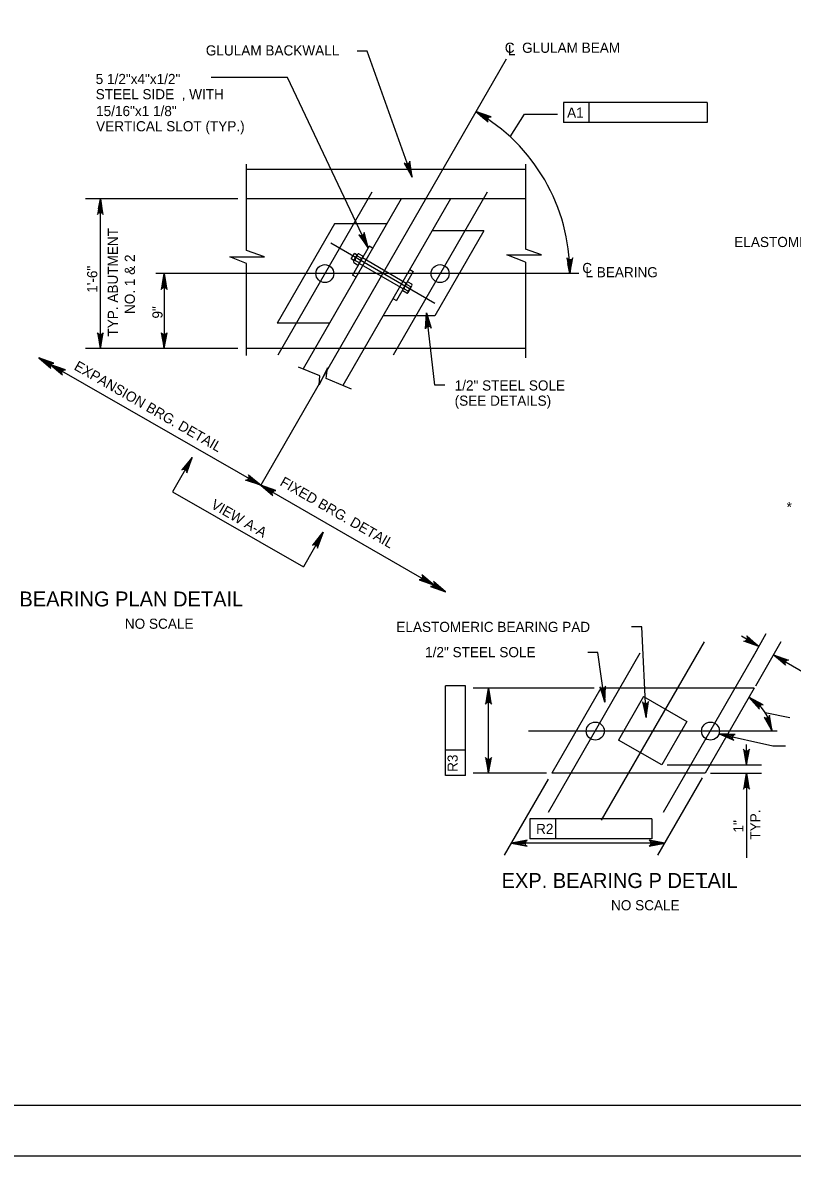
# Model space of a CAD drawing. Extents: x 638263 to 640391, y 293683 to 298655.
# Drawn here: x 638494.1 to 638721.7, y 293683.5 to 294018.7 of the extents above; entities that cross this region are included whole.
import ezdxf

# ---------------------------------------------------------------- set-up
doc = ezdxf.new("R2010")
doc.units = 0
for name, color, linetype in [('2', 7, 'Continuous'), ('3', 7, 'Continuous'), ('4', 7, 'Continuous'), ('5', 7, 'Continuous'), ('PLT-BNDY', 7, 'Continuous')]:
    doc.layers.add(name, color=color, linetype=linetype)

msp = doc.modelspace()

# ---------------------------------------------------------------- linework, layer by layer
at = {"layer": '2'}
msp.add_line((639261.46, 293698.46), (638475.46, 293698.46), dxfattribs=at)
at = {"layer": '3'}
for p, q in [((638637.06, 294007.91), (638564.52, 293881.93)), ((638560.31, 293951.36), (638560.31, 293976.89)), ((638642.78, 293976.89), (638642.78, 293951.74)), ((638642.78, 293975.28), (638560.31, 293975.28)), ((638642.78, 293966.67), (638560.31, 293966.67)), ((638597.37, 293968.64), (638569.6, 293920.41)), ((638606.09, 293966.67), (638577.03, 293916.33)), ((638620.65, 293966.67), (638588.78, 293911.46)), ((638631.45, 293968.64), (638603.67, 293920.41)), ((638586.31, 293959.29), (638569.39, 293929.9)), ((638601.83, 293959.29), (638586.31, 293959.29)), ((638630.52, 293957.16), (638615.17, 293957.16)), ((638630.52, 293957.16), (638616.05, 293932.03)), ((638616.03, 293935.64), (638585.24, 293953.53)), ((638596.61, 293952.61), (638591.69, 293944.08)), ((638597.61, 293952.03), (638596.61, 293952.61)), ((638560.31, 293947.52), (638555.4, 293949.52)), ((638555.4, 293949.52), (638565.67, 293949.52)), ((638565.67, 293949.52), (638560.31, 293951.36)), ((638591.3, 293948.86), (638592.23, 293950.46)), ((638592.09, 293948.41), (638591.3, 293948.86)), ((638591.99, 293948.23), (638593.12, 293950.2)), ((638593.01, 293950.01), (638592.23, 293950.46)), ((638594.27, 293949.08), (638593.15, 293949.72)), ((638593.54, 293950.39), (638594.66, 293949.75)), ((638593.56, 293947.32), (638594.7, 293949.29)), ((638607.56, 293941.63), (638594.61, 293949.15)), ((638637.27, 293950.11), (638647.54, 293950.11)), ((638642.78, 293947.87), (638637.27, 293950.11)), ((638647.54, 293950.11), (638642.78, 293951.74)), ((638560.31, 293920.34), (638560.31, 293947.52)), ((638592.04, 293947.8), (638593.16, 293947.16)), ((638593.52, 293947.78), (638592.4, 293948.42)), ((638606.63, 293940.01), (638593.68, 293947.53)), ((638608.58, 293945.7), (638609.58, 293945.12)), ((638642.78, 293947.87), (638642.78, 293919.65)), ((638592.73, 293943.48), (638591.69, 293944.08)), ((638609.58, 293945.12), (638604.66, 293936.6)), ((638606.53, 293939.84), (638607.66, 293941.81)), ((638607.7, 293938.76), (638606.58, 293939.41)), ((638606.95, 293940.03), (638608.06, 293939.39)), ((638607.69, 293941.33), (638608.81, 293940.69)), ((638609.2, 293941.36), (638608.08, 293942)), ((638608.1, 293938.93), (638609.24, 293940.9)), ((638603.61, 293937.2), (638604.66, 293936.6)), ((638584.86, 293929.9), (638569.39, 293929.9)), ((638616.05, 293932.03), (638600.66, 293932.03)), ((638580.52, 293922.37), (638560.31, 293922.37)), ((638595.08, 293922.37), (638580.52, 293922.37)), ((638642.78, 293922.37), (638595.08, 293922.37)), ((638695.64, 293835.63), (638665.23, 293782.83)), ((638676.62, 293832.26), (638649.47, 293785.12)), ((638711.32, 293833.35), (638683.55, 293785.12)), ((638665.04, 293821.88), (638650.56, 293796.75)), ((638710.39, 293821.88), (638665.04, 293821.88)), ((638710.39, 293821.88), (638695.92, 293796.75)), ((638677.74, 293819.42), (638670.35, 293806.57)), ((638677.74, 293819.42), (638690.54, 293812.05)), ((638690.54, 293812.05), (638683.14, 293799.21)), ((638683.14, 293799.21), (638670.35, 293806.57)), ((638695.92, 293796.75), (638650.56, 293796.75))]:
    msp.add_line(p, q, dxfattribs=at)
for points in [[(638631.86, 293821.88), (638630.99, 293817.22), (638631.24, 293817.57), (638631.55, 293817.76), (638631.86, 293817.81), (638632.17, 293817.76), (638632.49, 293817.57), (638632.73, 293817.22), (638631.86, 293821.88), (638632.49, 293817.57), (638632.17, 293817.76), (638631.86, 293821.88), (638631.86, 293817.81), (638631.55, 293817.76), (638631.86, 293821.88), (638631.24, 293817.57)], [(638666.3, 293817.79), (638666.51, 293822.53), (638666.31, 293822.14), (638666.03, 293821.91), (638665.73, 293821.82), (638665.41, 293821.83), (638665.08, 293821.96), (638664.78, 293822.28), (638666.3, 293817.79), (638665.08, 293821.96), (638665.41, 293821.83), (638666.3, 293817.79), (638665.73, 293821.82), (638666.03, 293821.91), (638666.3, 293817.79), (638666.31, 293822.14)], [(638708.87, 293819.24), (638711.98, 293815.66), (638711.85, 293816.07), (638711.9, 293816.43), (638712.06, 293816.71), (638712.29, 293816.92), (638712.63, 293817.05), (638713.07, 293817.03), (638708.87, 293819.24), (638712.63, 293817.05), (638712.29, 293816.92), (638708.87, 293819.24), (638712.06, 293816.71), (638711.9, 293816.43), (638708.87, 293819.24), (638711.85, 293816.07)], [(638678.54, 293813.27), (638679.18, 293817.97), (638678.95, 293817.59), (638678.64, 293817.39), (638678.34, 293817.33), (638678.02, 293817.36), (638677.7, 293817.53), (638677.43, 293817.88), (638678.54, 293813.27), (638677.7, 293817.53), (638678.02, 293817.36), (638678.54, 293813.27), (638678.34, 293817.33), (638678.64, 293817.39), (638678.54, 293813.27), (638678.95, 293817.59)], [(638715.73, 293809.24), (638715, 293813.92), (638714.89, 293813.5), (638714.65, 293813.22), (638714.38, 293813.07), (638714.07, 293813.01), (638713.71, 293813.08), (638713.36, 293813.34), (638715.73, 293809.24), (638713.71, 293813.08), (638714.07, 293813.01), (638715.73, 293809.24), (638714.38, 293813.07), (638714.65, 293813.22), (638715.73, 293809.24), (638714.89, 293813.5)], [(638700.03, 293808.4), (638704.39, 293806.55), (638704.1, 293806.87), (638703.98, 293807.21), (638704, 293807.53), (638704.12, 293807.82), (638704.36, 293808.09), (638704.77, 293808.25), (638700.03, 293808.4), (638704.36, 293808.09), (638704.12, 293807.82), (638700.03, 293808.4), (638704, 293807.53), (638703.98, 293807.21), (638700.03, 293808.4), (638704.1, 293806.87)], [(638631.86, 293796.75), (638632.73, 293801.41), (638632.49, 293801.05), (638632.17, 293800.86), (638631.86, 293800.81), (638631.55, 293800.86), (638631.24, 293801.05), (638630.99, 293801.41), (638631.86, 293796.75), (638631.24, 293801.05), (638631.55, 293800.86), (638631.86, 293796.75), (638631.86, 293800.81), (638632.17, 293800.86), (638631.86, 293796.75), (638632.49, 293801.05)], [(638708.14, 293799.21), (638709.01, 293803.87), (638708.76, 293803.51), (638708.45, 293803.32), (638708.14, 293803.27), (638707.83, 293803.32), (638707.51, 293803.51), (638707.26, 293803.87), (638708.14, 293799.21), (638707.51, 293803.51), (638707.83, 293803.32), (638708.14, 293799.21), (638708.14, 293803.27), (638708.45, 293803.32), (638708.14, 293799.21), (638708.76, 293803.51)], [(638708.14, 293796.75), (638707.26, 293792.09), (638707.51, 293792.44), (638707.83, 293792.63), (638708.14, 293792.68), (638708.45, 293792.63), (638708.76, 293792.44), (638709.01, 293792.09), (638708.14, 293796.75), (638708.76, 293792.44), (638708.45, 293792.63), (638708.14, 293796.75), (638708.14, 293792.68), (638707.83, 293792.63), (638708.14, 293796.75), (638707.51, 293792.44)], [(638638.65, 293776.05), (638643.31, 293775.18), (638642.95, 293775.43), (638642.76, 293775.74), (638642.71, 293776.05), (638642.76, 293776.36), (638642.95, 293776.68), (638643.31, 293776.92), (638638.65, 293776.05), (638642.95, 293776.68), (638642.76, 293776.36), (638638.65, 293776.05), (638642.71, 293776.05), (638642.76, 293775.74), (638638.65, 293776.05), (638642.95, 293775.43)], [(638684, 293776.05), (638679.34, 293776.92), (638679.7, 293776.68), (638679.89, 293776.36), (638679.94, 293776.05), (638679.89, 293775.74), (638679.7, 293775.43), (638679.34, 293775.18), (638684, 293776.05), (638679.7, 293775.43), (638679.89, 293775.74), (638684, 293776.05), (638679.94, 293776.05), (638679.89, 293776.36), (638684, 293776.05), (638679.7, 293776.68)]]:
    msp.add_lwpolyline(points, dxfattribs=at)
for centre in [(638583.49, 293944.52), (638617.56, 293944.52), (638663.43, 293809.23), (638697.51, 293809.23)]:
    msp.add_circle(centre, 2.66, dxfattribs=at)
for centre, radius, start, end in [((638593.58, 293948.61), 1.19, 111.021, 188.921), ((638593.48, 293949.98), 0.417, 151.798, 218.684), ((638593.48, 293949.98), 0.417, 81.2579, 151.798), ((638593.09, 293948.89), 1.19, 291.021, 8.921), ((638594.33, 293949.49), 0.417, 261.2579, 328.1439), ((638594.33, 293949.49), 0.417, 328.1439, 38.684), ((638592.32, 293948.06), 0.379, 77.4228, 222.5192), ((638593.24, 293947.53), 0.379, 257.4228, 42.5192), ((638606.86, 293939.66), 0.379, 77.4808, 222.5772), ((638608.12, 293940.22), 1.19, 111.079, 188.979), ((638608.02, 293941.59), 0.417, 151.8561, 218.7421), ((638608.02, 293941.59), 0.417, 81.3159, 151.8561), ((638607.78, 293939.13), 0.379, 257.4808, 42.5772), ((638607.63, 293940.5), 1.19, 291.079, 8.979), ((638608.87, 293941.1), 0.417, 261.3159, 328.2019), ((638608.87, 293941.1), 0.417, 328.2019, 38.7421)]:
    msp.add_arc(centre, radius, start, end, dxfattribs=at)
at = {"layer": '4'}
for p, q in [((638596.03, 294010.31), (638593.08, 294010.31)), ((638609.33, 293973.08), (638596.03, 294010.31)), ((638572.41, 294002.56), (638549.84, 294002.56)), ((638596.33, 293952.12), (638572.41, 294002.56)), ((638654.01, 293995.11), (638654.01, 293989.2)), ((638688.96, 293995.11), (638654.01, 293995.11)), ((638661.57, 293995.11), (638654.01, 293995.11)), ((638661.57, 293995.11), (638661.57, 293989.2)), ((638696.53, 293995.11), (638688.96, 293995.11)), ((638696.53, 293995.11), (638696.53, 293989.2)), ((638638.27, 293985.01), (638642.5, 293991.68)), ((638642.5, 293991.68), (638652.23, 293991.68)), ((638696.53, 293989.2), (638654.01, 293989.2)), ((638557.78, 293966.67), (638512.68, 293966.67)), ((638517.11, 293922.37), (638517.11, 293966.67)), ((638658.61, 293944.52), (638533.49, 293944.52)), ((638535.98, 293944.52), (638535.98, 293922.37)), ((638615.97, 293911.53), (638613.59, 293932.97)), ((638557.78, 293922.37), (638512.68, 293922.37)), ((638555.34, 293922.37), (638529.08, 293922.37)), ((638536.42, 293922.37), (638531.55, 293922.37)), ((638555.34, 293922.37), (638531.76, 293922.37)), ((638498.91, 293919.59), (638564.52, 293881.93)), ((638582.02, 293914.29), (638575.7, 293916.88)), ((638584.25, 293916.62), (638581.85, 293911.64)), ((638583.91, 293913.5), (638584.25, 293916.62)), ((638581.85, 293911.64), (638582.02, 293914.29)), ((638591.41, 293910.36), (638583.91, 293913.5)), ((638618.93, 293911.53), (638615.97, 293911.53)), ((638544.27, 293890.12), (638538.45, 293880)), ((638538.45, 293880), (638577.13, 293857.79)), ((638565.18, 293881.55), (638619.21, 293850.37)), ((638582.91, 293867.83), (638577.13, 293857.79)), ((638677.2, 293840.05), (638674.2, 293840.05)), ((638678.54, 293813.27), (638677.2, 293840.05)), ((638711.83, 293834.28), (638706.65, 293837.26)), ((638710.1, 293831.22), (638713.98, 293838.05)), ((638710.91, 293822.59), (638718.36, 293835.71)), ((638664.2, 293832.47), (638661.2, 293832.47)), ((638666.3, 293817.79), (638664.2, 293832.47)), ((638716.15, 293831.82), (638733.44, 293821.66)), ((638619.12, 293796.05), (638619.12, 293822.59)), ((638625.03, 293822.59), (638619.12, 293822.59)), ((638625.03, 293803.61), (638625.03, 293822.59)), ((638663.09, 293821.88), (638627.36, 293821.88)), ((638631.86, 293796.75), (638631.86, 293821.88)), ((638713.63, 293814.72), (638720.94, 293813.26)), ((638717.18, 293809.23), (638643.69, 293809.23)), ((638700.03, 293808.4), (638715.98, 293804.89)), ((638708.14, 293799.21), (638708.14, 293805.21)), ((638715.98, 293804.89), (638719.68, 293804.89)), ((638625.03, 293803.61), (638619.12, 293803.61)), ((638625.03, 293796.05), (638625.03, 293803.61)), ((638684.7, 293799.21), (638712.64, 293799.21)), ((638625.03, 293796.05), (638619.12, 293796.05)), ((638649, 293796.75), (638627.36, 293796.75)), ((638636.63, 293772.54), (638649.58, 293795.04)), ((638681.98, 293772.54), (638695.13, 293795.37)), ((638697.48, 293796.75), (638712.64, 293796.75)), ((638708.14, 293796.75), (638708.14, 293771.78)), ((638644.12, 293783.25), (638644.12, 293777.34)), ((638672.61, 293783.25), (638644.12, 293783.25)), ((638651.68, 293783.25), (638644.12, 293783.25)), ((638651.68, 293783.25), (638651.68, 293777.34)), ((638680.18, 293783.25), (638672.61, 293783.25)), ((638680.18, 293783.25), (638680.18, 293777.34)), ((638684, 293776.05), (638638.65, 293776.05)), ((638680.18, 293777.34), (638644.12, 293777.34))]:
    msp.add_line(p, q, dxfattribs=at)
for points in [[(638628.15, 293992.44), (638631.76, 293989.37), (638631.58, 293989.76), (638631.57, 293990.12), (638631.68, 293990.42), (638631.88, 293990.67), (638632.2, 293990.85), (638632.63, 293990.88), (638628.15, 293992.44), (638632.2, 293990.85), (638631.88, 293990.67), (638628.15, 293992.44), (638631.68, 293990.42), (638631.57, 293990.12), (638628.15, 293992.44), (638631.58, 293989.76)], [(638609.33, 293973.08), (638608.58, 293977.77), (638608.47, 293977.34), (638608.24, 293977.06), (638607.96, 293976.91), (638607.65, 293976.85), (638607.29, 293976.92), (638606.94, 293977.18), (638609.33, 293973.08), (638607.29, 293976.92), (638607.65, 293976.85), (638609.33, 293973.08), (638607.96, 293976.91), (638608.24, 293977.06), (638609.33, 293973.08), (638608.47, 293977.34)], [(638517.11, 293966.67), (638516.23, 293962.01), (638516.48, 293962.37), (638516.79, 293962.55), (638517.11, 293962.61), (638517.42, 293962.55), (638517.73, 293962.37), (638517.98, 293962.01), (638517.11, 293966.67), (638517.73, 293962.37), (638517.42, 293962.55), (638517.11, 293966.67), (638517.11, 293962.61), (638516.79, 293962.55), (638517.11, 293966.67), (638516.48, 293962.37)], [(638596.33, 293952.12), (638595.12, 293956.7), (638595.05, 293956.27), (638594.85, 293955.97), (638594.59, 293955.79), (638594.28, 293955.7), (638593.92, 293955.74), (638593.54, 293955.96), (638596.33, 293952.12), (638593.92, 293955.74), (638594.28, 293955.7), (638596.33, 293952.12), (638594.59, 293955.79), (638594.85, 293955.97), (638596.33, 293952.12), (638595.05, 293956.27)], [(638655.95, 293944.52), (638656.82, 293949.18), (638656.57, 293948.82), (638656.26, 293948.63), (638655.95, 293948.58), (638655.64, 293948.63), (638655.32, 293948.82), (638655.08, 293949.18), (638655.95, 293944.52), (638655.32, 293948.82), (638655.64, 293948.63), (638655.95, 293944.52), (638655.95, 293948.58), (638656.26, 293948.63), (638655.95, 293944.52), (638656.57, 293948.82)], [(638535.98, 293944.52), (638535.11, 293939.86), (638535.36, 293940.22), (638535.67, 293940.4), (638535.98, 293940.46), (638536.29, 293940.4), (638536.61, 293940.22), (638536.85, 293939.86), (638535.98, 293944.52), (638536.61, 293940.22), (638536.29, 293940.4), (638535.98, 293944.52), (638535.98, 293940.46), (638535.67, 293940.4), (638535.98, 293944.52), (638535.36, 293940.22)], [(638613.59, 293932.97), (638614.97, 293928.43), (638614.68, 293928.76), (638614.35, 293928.91), (638614.04, 293928.93), (638613.73, 293928.84), (638613.44, 293928.62), (638613.23, 293928.24), (638613.59, 293932.97), (638613.44, 293928.62), (638613.73, 293928.84), (638613.59, 293932.97), (638614.04, 293928.93), (638614.35, 293928.91), (638613.59, 293932.97), (638614.68, 293928.76)], [(638517.11, 293922.37), (638517.98, 293927.03), (638517.73, 293926.68), (638517.42, 293926.49), (638517.11, 293926.44), (638516.79, 293926.49), (638516.48, 293926.68), (638516.23, 293927.03), (638517.11, 293922.37), (638516.48, 293926.68), (638516.79, 293926.49), (638517.11, 293922.37), (638517.11, 293926.44), (638517.42, 293926.49), (638517.11, 293922.37), (638517.73, 293926.68)], [(638535.98, 293922.37), (638536.85, 293927.03), (638536.61, 293926.68), (638536.29, 293926.49), (638535.98, 293926.44), (638535.67, 293926.49), (638535.36, 293926.68), (638535.11, 293927.03), (638535.98, 293922.37), (638535.36, 293926.68), (638535.67, 293926.49), (638535.98, 293922.37), (638535.98, 293926.44), (638536.29, 293926.49), (638535.98, 293922.37), (638536.61, 293926.68)], [(638498.91, 293919.59), (638502.52, 293916.52), (638502.33, 293916.91), (638502.33, 293917.27), (638502.44, 293917.57), (638502.64, 293917.82), (638502.95, 293917.99), (638503.39, 293918.03), (638498.91, 293919.59), (638502.95, 293917.99), (638502.64, 293917.82), (638498.91, 293919.59), (638502.44, 293917.57), (638502.33, 293917.27), (638498.91, 293919.59), (638502.33, 293916.91)], [(638502.31, 293917.67), (638505.92, 293914.59), (638505.73, 293914.98), (638505.72, 293915.35), (638505.83, 293915.64), (638506.04, 293915.89), (638506.35, 293916.07), (638506.79, 293916.11), (638502.31, 293917.67), (638506.35, 293916.07), (638506.04, 293915.89), (638502.31, 293917.67), (638505.83, 293915.64), (638505.72, 293915.35), (638502.31, 293917.67), (638505.73, 293914.98)], [(638544.27, 293890.12), (638541.19, 293886.52), (638541.58, 293886.7), (638541.95, 293886.71), (638542.24, 293886.6), (638542.49, 293886.39), (638542.67, 293886.08), (638542.7, 293885.64), (638544.27, 293890.12), (638542.67, 293886.08), (638542.49, 293886.39), (638544.27, 293890.12), (638542.24, 293886.6), (638541.95, 293886.71), (638544.27, 293890.12), (638541.58, 293886.7)], [(638564.52, 293881.93), (638560.03, 293883.46), (638560.47, 293883.5), (638560.78, 293883.68), (638560.98, 293883.93), (638561.09, 293884.23), (638561.08, 293884.59), (638560.89, 293884.98), (638564.52, 293881.93), (638561.08, 293884.59), (638561.09, 293884.23), (638564.52, 293881.93), (638560.98, 293883.93), (638560.78, 293883.68), (638564.52, 293881.93), (638560.47, 293883.5)], [(638564.52, 293881.93), (638568.15, 293878.88), (638567.96, 293879.27), (638567.95, 293879.64), (638568.06, 293879.94), (638568.26, 293880.18), (638568.57, 293880.36), (638569.01, 293880.4), (638564.52, 293881.93), (638568.57, 293880.36), (638568.26, 293880.18), (638564.52, 293881.93), (638568.06, 293879.94), (638567.95, 293879.64), (638564.52, 293881.93), (638567.96, 293879.27)], [(638582.91, 293867.83), (638579.82, 293864.23), (638580.22, 293864.41), (638580.58, 293864.42), (638580.88, 293864.31), (638581.12, 293864.11), (638581.3, 293863.79), (638581.34, 293863.35), (638582.91, 293867.83), (638581.3, 293863.79), (638581.12, 293864.11), (638582.91, 293867.83), (638580.88, 293864.31), (638580.58, 293864.42), (638582.91, 293867.83), (638580.22, 293864.41)], [(638615.81, 293852.4), (638612.21, 293855.48), (638612.39, 293855.09), (638612.4, 293854.73), (638612.29, 293854.43), (638612.09, 293854.18), (638611.77, 293854.01), (638611.33, 293853.97), (638615.81, 293852.4), (638611.77, 293854.01), (638612.09, 293854.18), (638615.81, 293852.4), (638612.29, 293854.43), (638612.4, 293854.73), (638615.81, 293852.4), (638612.39, 293855.09)], [(638619.21, 293850.37), (638615.61, 293853.45), (638615.8, 293853.06), (638615.8, 293852.69), (638615.69, 293852.4), (638615.49, 293852.15), (638615.18, 293851.98), (638614.74, 293851.94), (638619.21, 293850.37), (638615.18, 293851.98), (638615.49, 293852.15), (638619.21, 293850.37), (638615.69, 293852.4), (638615.8, 293852.69), (638619.21, 293850.37), (638615.8, 293853.06)], [(638711.83, 293834.28), (638707.36, 293835.85), (638707.79, 293835.88), (638708.11, 293836.06), (638708.31, 293836.31), (638708.42, 293836.6), (638708.42, 293836.97), (638708.23, 293837.36), (638711.83, 293834.28), (638708.42, 293836.97), (638708.42, 293836.6), (638711.83, 293834.28), (638708.31, 293836.31), (638708.11, 293836.06), (638711.83, 293834.28), (638707.79, 293835.88)], [(638716.15, 293831.82), (638720.61, 293830.21), (638720.18, 293830.18), (638719.86, 293830.01), (638719.65, 293829.76), (638719.54, 293829.47), (638719.54, 293829.11), (638719.73, 293828.71), (638716.15, 293831.82), (638719.54, 293829.11), (638719.54, 293829.47), (638716.15, 293831.82), (638719.65, 293829.76), (638719.86, 293830.01), (638716.15, 293831.82), (638720.18, 293830.18)]]:
    msp.add_lwpolyline(points, dxfattribs=at)
for points in [[(638517.6, 293963.71), (638516.61, 293963.71), (638517.11, 293966.67)], [(638536.47, 293941.57), (638535.49, 293941.57), (638535.98, 293944.52)], [(638536.47, 293925.33), (638535.49, 293925.33), (638535.98, 293922.37)], [(638562.17, 293883.86), (638561.67, 293883), (638564.52, 293881.93)], [(638567.37, 293880.87), (638566.87, 293880), (638564.52, 293881.93)], [(638581.76, 293864.64), (638580.72, 293865.24), (638583.04, 293868.06)], [(638632.36, 293818.88), (638631.36, 293818.88), (638631.86, 293821.88)], [(638703.06, 293808.25), (638702.84, 293807.27), (638700.02, 293808.41)], [(638708.64, 293802.21), (638707.64, 293802.21), (638708.14, 293799.21)], [(638632.36, 293799.75), (638631.36, 293799.75), (638631.86, 293796.75)], [(638708.64, 293793.75), (638707.64, 293793.75), (638708.14, 293796.75)], [(638641.65, 293776.55), (638641.65, 293775.55), (638638.65, 293776.05)], [(638681, 293776.55), (638681, 293775.55), (638684, 293776.05)]]:
    msp.add_lwpolyline(points, close=True, dxfattribs=at)
msp.add_arc((638701.89, 293807.11), 14, 8.7466, 60.0642, dxfattribs=at)
at = {"layer": '5'}
for points in [[(638630.97, 293991.28), (638630.44, 293990.43), (638628.15, 293992.44)], [(638655.35, 293947.5), (638656.35, 293947.53), (638655.95, 293944.52)]]:
    msp.add_lwpolyline(points, close=True, dxfattribs=at)
msp.add_arc((638600.74, 293944.52), 55.2, 0, 60.2299, dxfattribs=at)
at = {"layer": 'PLT-BNDY'}
msp.add_lwpolyline([(638435.46, 294277.46), (639276.46, 294277.46), (639276.46, 293683.46), (638435.46, 293683.46)], close=True, dxfattribs=at)

# ---------------------------------------------------------------- texts
at = {"layer": '4'}
for s, height, p in [('C  GLULAM BEAM', 3, (638636.69, 294009.83)), ('GLULAM BACKWALL', 3, (638548.3, 294009.04)), ('L', 3, (638637.59, 294009.11)), ('5 1/2"x4"x1/2"', 3, (638515.74, 294000.59)), ('STEEL SIDE  , WITH', 3, (638515.74, 293996.09)), ('15/16"x1 1/8"', 3, (638515.86, 293991.11)), ('VERTICAL SLOT (TYP.)', 3, (638515.86, 293986.61)), ('ELASTOMERIC BEARING PAD', 3, (638704.55, 293952.38)), ('C', 3, (638659.6, 293944.69)), ('L BEARING', 3, (638660.54, 293943.44)), ('1/2" STEEL SOLE  ', 3, (638621.87, 293909.95)), ('(SEE DETAILS)', 3, (638621.87, 293905.45)), ('*', 3, (638720.01, 293874)), ('BEARING PLAN DETAIL', 4.4292, (638493.18, 293846.08)), ('NO SCALE', 3, (638524.36, 293839.48)), ('ELASTOMERIC BEARING PAD', 3, (638604.63, 293838.54)), ('1/2" STEEL SOLE  ', 3, (638613.14, 293831.08)), ('EXP. BEARING P DETAIL', 4.4292, (638635.75, 293762.81)), ('L', 3, (638694.51, 293762.79)), ('NO SCALE', 3, (638668.1, 293756.22))]:
    msp.add_text(s, height=height, dxfattribs=at).set_placement(p)
for s, rotation, p in [('A1', 0.0618, (638655.11, 293990.65)), ('TYP. ABUTMENT', 90, (638522.3, 293925.91)), ('NO. 1 & 2', 90, (638527.32, 293932.57)), ('1\'-6"', 90, (638516.21, 293938.85)), ('9"', 90, (638535.5, 293931.23)), ('EXPANSION BRG. DETAIL', 330.0642, (638509.09, 293916.3)), ('FIXED BRG. DETAIL', 330.0642, (638569.96, 293882.04)), ('VIEW A-A', 330.0642, (638549.56, 293875.34)), ('R3', 89.9382, (638622.76, 293797.15)), ('TYP.', 90, (638712.25, 293777.11)), ('R2', 0.0618, (638645.94, 293778.79)), ('1"', 90, (638707.27, 293779.23))]:
    msp.add_text(s, height=3, rotation=rotation, dxfattribs=at).set_placement(p)

doc.saveas('drawing.dxf')
